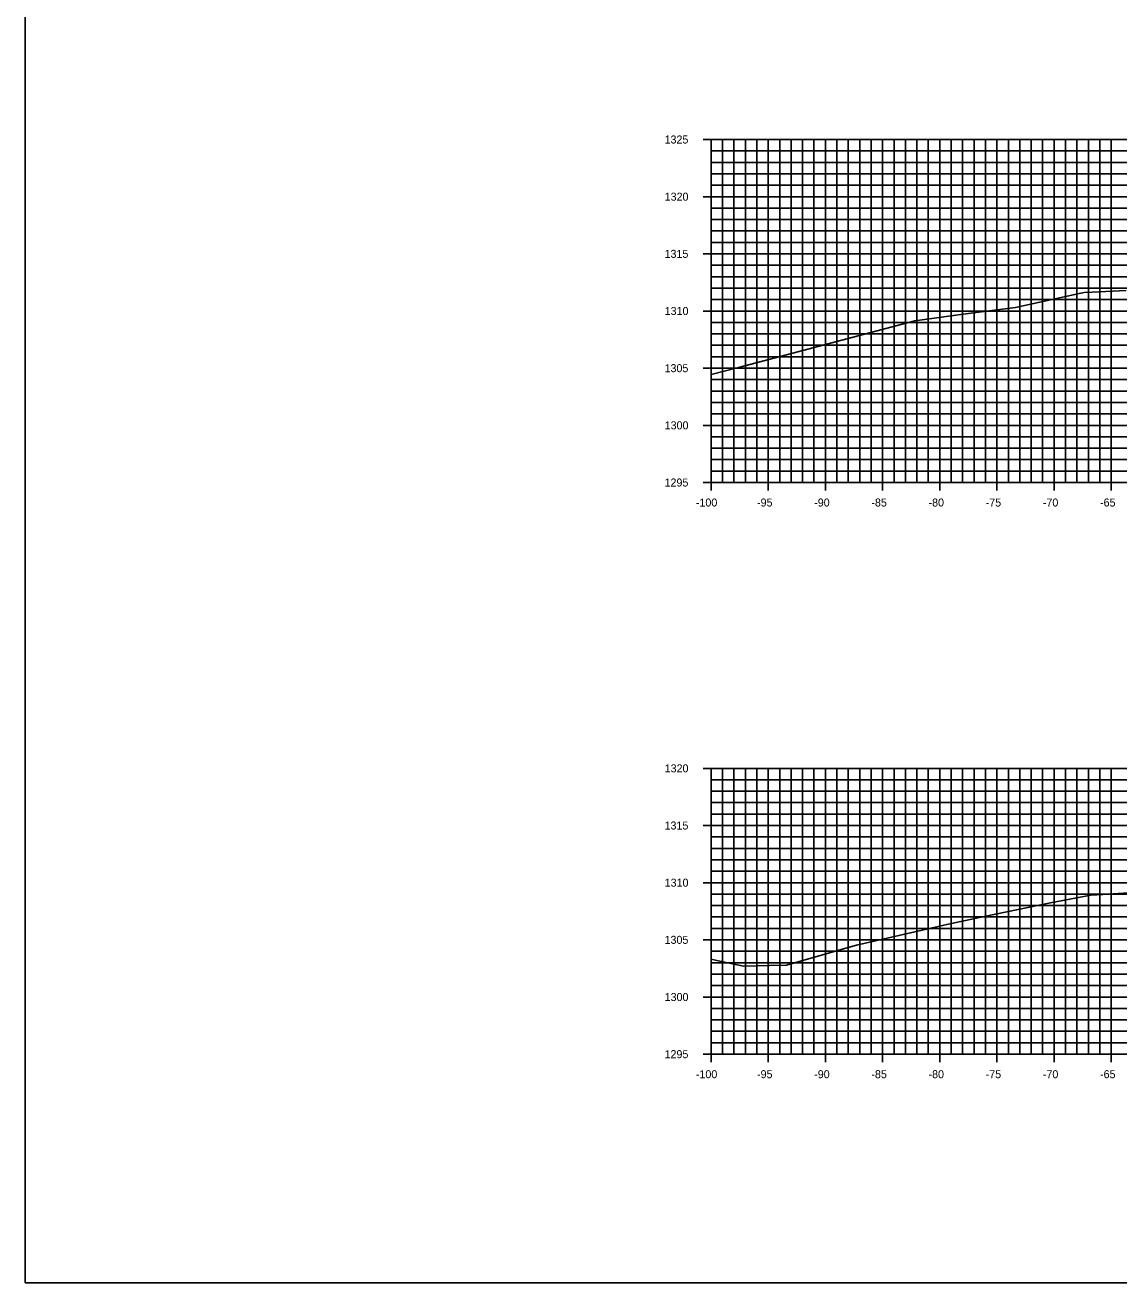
# Model space of a CAD drawing. Extents: x 674939 to 678919, y 750652 to 765176.
# Drawn here: x 678578.5 to 678674.2, y 751152.6 to 751262.6 of the extents above; entities that cross this region are included whole.
import ezdxf

# ---------------------------------------------------------------- set-up
doc = ezdxf.new("R2010")
doc.units = 0
for name, color, linetype in [('R_Axis', 7, 'Continuous'), ('R_Axis Annot', 7, 'Continuous'), ('R_Exist Surface', 7, 'Continuous'), ('R_Grid', 7, 'Continuous'), ('R_No Plot', 7, 'Continuous')]:
    doc.layers.add(name, color=color, linetype=linetype)

msp = doc.modelspace()

# ---------------------------------------------------------------- linework, layer by layer
at = {"layer": 'R_Axis'}
for p, q in [((678637.83, 751252.55), (678639.23, 751252.55)), ((678638.53, 751222.55), (678638.53, 751252.55)), ((678638.53, 751251.55), (678638.88, 751251.55)), ((678638.53, 751250.55), (678638.88, 751250.55)), ((678638.53, 751249.55), (678638.88, 751249.55)), ((678638.53, 751248.55), (678638.88, 751248.55)), ((678637.83, 751247.55), (678639.23, 751247.55)), ((678638.53, 751246.55), (678638.88, 751246.55)), ((678638.53, 751245.55), (678638.88, 751245.55)), ((678638.53, 751244.55), (678638.88, 751244.55)), ((678638.53, 751243.55), (678638.88, 751243.55)), ((678637.83, 751242.55), (678639.23, 751242.55)), ((678638.53, 751241.55), (678638.88, 751241.55)), ((678638.53, 751240.55), (678638.88, 751240.55)), ((678638.53, 751239.55), (678638.88, 751239.55)), ((678638.53, 751238.55), (678638.88, 751238.55)), ((678637.83, 751237.55), (678639.23, 751237.55)), ((678638.53, 751236.55), (678638.88, 751236.55)), ((678638.53, 751235.55), (678638.88, 751235.55)), ((678638.53, 751234.55), (678638.88, 751234.55)), ((678638.53, 751233.55), (678638.88, 751233.55)), ((678637.83, 751232.55), (678639.23, 751232.55)), ((678638.53, 751231.55), (678638.88, 751231.55)), ((678638.53, 751230.55), (678638.88, 751230.55)), ((678638.53, 751229.55), (678638.88, 751229.55)), ((678638.53, 751228.55), (678638.88, 751228.55)), ((678637.83, 751227.55), (678639.23, 751227.55)), ((678638.53, 751226.55), (678638.88, 751226.55)), ((678638.53, 751225.55), (678638.88, 751225.55)), ((678638.53, 751224.55), (678638.88, 751224.55)), ((678638.53, 751223.55), (678638.88, 751223.55)), ((678638.53, 751221.85), (678638.53, 751223.25)), ((678643.53, 751221.85), (678643.53, 751223.25)), ((678648.53, 751221.85), (678648.53, 751223.25)), ((678653.53, 751221.85), (678653.53, 751223.25)), ((678658.53, 751221.85), (678658.53, 751223.25)), ((678663.53, 751221.85), (678663.53, 751223.25)), ((678668.53, 751221.85), (678668.53, 751223.25)), ((678673.53, 751221.85), (678673.53, 751223.25)), ((678637.83, 751222.55), (678639.23, 751222.55)), ((678638.53, 751222.55), (678838.53, 751222.55)), ((678637.83, 751197.55), (678639.23, 751197.55)), ((678638.53, 751172.55), (678638.53, 751197.55)), ((678638.53, 751196.55), (678638.88, 751196.55)), ((678638.53, 751195.55), (678638.88, 751195.55)), ((678638.53, 751194.55), (678638.88, 751194.55)), ((678638.53, 751193.55), (678638.88, 751193.55)), ((678637.83, 751192.55), (678639.23, 751192.55)), ((678638.53, 751191.55), (678638.88, 751191.55)), ((678638.53, 751190.55), (678638.88, 751190.55)), ((678638.53, 751189.55), (678638.88, 751189.55)), ((678638.53, 751188.55), (678638.88, 751188.55)), ((678637.83, 751187.55), (678639.23, 751187.55)), ((678638.53, 751186.55), (678638.88, 751186.55)), ((678638.53, 751185.55), (678638.88, 751185.55)), ((678638.53, 751184.55), (678638.88, 751184.55)), ((678638.53, 751183.55), (678638.88, 751183.55)), ((678637.83, 751182.55), (678639.23, 751182.55)), ((678638.53, 751181.55), (678638.88, 751181.55)), ((678638.53, 751180.55), (678638.88, 751180.55)), ((678638.53, 751179.55), (678638.88, 751179.55)), ((678638.53, 751178.55), (678638.88, 751178.55)), ((678637.83, 751177.55), (678639.23, 751177.55)), ((678638.53, 751176.55), (678638.88, 751176.55)), ((678638.53, 751175.55), (678638.88, 751175.55)), ((678638.53, 751174.55), (678638.88, 751174.55)), ((678638.53, 751173.55), (678638.88, 751173.55)), ((678637.83, 751172.55), (678639.23, 751172.55)), ((678638.53, 751171.85), (678638.53, 751173.25)), ((678638.53, 751172.55), (678838.53, 751172.55)), ((678643.53, 751171.85), (678643.53, 751173.25)), ((678648.53, 751171.85), (678648.53, 751173.25)), ((678653.53, 751171.85), (678653.53, 751173.25)), ((678658.53, 751171.85), (678658.53, 751173.25)), ((678663.53, 751171.85), (678663.53, 751173.25)), ((678668.53, 751171.85), (678668.53, 751173.25)), ((678673.53, 751171.85), (678673.53, 751173.25))]:
    msp.add_line(p, q, dxfattribs=at)
at = {"layer": 'R_Exist Surface'}
for points in [[(678638.53, 751232.01), (678640.94, 751232.6), (678644.56, 751233.56), (678656.36, 751236.69), (678660.59, 751237.27), (678665.16, 751237.87), (678670.87, 751239.11), (678671.06, 751239.15), (678671.15, 751239.16), (678671.87, 751239.19), (678674.84, 751239.35)], [(678638.53, 751180.85), (678639.03, 751180.75), (678641.37, 751180.24), (678643.64, 751180.31), (678645.14, 751180.33), (678648.68, 751181.35), (678651.24, 751182.08), (678657, 751183.39), (678659.14, 751183.9), (678662.42, 751184.58), (678668.22, 751185.78), (678671.75, 751186.47), (678672.8, 751186.53), (678675.04, 751186.67)]]:
    msp.add_lwpolyline(points, dxfattribs=at)
at = {"layer": 'R_Grid'}
for p, q in [((678638.53, 751252.55), (678838.53, 751252.55)), ((678638.53, 751222.55), (678638.53, 751252.55)), ((678639.53, 751222.55), (678639.53, 751252.55)), ((678640.53, 751222.55), (678640.53, 751252.55)), ((678641.53, 751222.55), (678641.53, 751252.55)), ((678642.53, 751222.55), (678642.53, 751252.55)), ((678643.53, 751222.55), (678643.53, 751252.55)), ((678644.53, 751222.55), (678644.53, 751252.55)), ((678645.53, 751222.55), (678645.53, 751252.55)), ((678646.53, 751222.55), (678646.53, 751252.55)), ((678647.53, 751222.55), (678647.53, 751252.55)), ((678648.53, 751222.55), (678648.53, 751252.55)), ((678649.53, 751222.55), (678649.53, 751252.55)), ((678650.53, 751222.55), (678650.53, 751252.55)), ((678651.53, 751222.55), (678651.53, 751252.55)), ((678652.53, 751222.55), (678652.53, 751252.55)), ((678653.53, 751222.55), (678653.53, 751252.55)), ((678654.53, 751222.55), (678654.53, 751252.55)), ((678655.53, 751222.55), (678655.53, 751252.55)), ((678656.53, 751222.55), (678656.53, 751252.55)), ((678657.53, 751222.55), (678657.53, 751252.55)), ((678658.53, 751222.55), (678658.53, 751252.55)), ((678659.53, 751222.55), (678659.53, 751252.55)), ((678660.53, 751222.55), (678660.53, 751252.55)), ((678661.53, 751222.55), (678661.53, 751252.55)), ((678662.53, 751222.55), (678662.53, 751252.55)), ((678663.53, 751222.55), (678663.53, 751252.55)), ((678664.53, 751222.55), (678664.53, 751252.55)), ((678665.53, 751222.55), (678665.53, 751252.55)), ((678666.53, 751222.55), (678666.53, 751252.55)), ((678667.53, 751222.55), (678667.53, 751252.55)), ((678668.53, 751222.55), (678668.53, 751252.55)), ((678669.53, 751222.55), (678669.53, 751252.55)), ((678670.53, 751222.55), (678670.53, 751252.55)), ((678671.53, 751222.55), (678671.53, 751252.55)), ((678672.53, 751222.55), (678672.53, 751252.55)), ((678673.53, 751222.55), (678673.53, 751252.55)), ((678638.53, 751251.55), (678838.53, 751251.55)), ((678638.53, 751250.55), (678838.53, 751250.55)), ((678638.53, 751249.55), (678838.53, 751249.55)), ((678638.53, 751248.55), (678838.53, 751248.55)), ((678638.53, 751247.55), (678838.53, 751247.55)), ((678638.53, 751246.55), (678838.53, 751246.55)), ((678638.53, 751245.55), (678838.53, 751245.55)), ((678638.53, 751244.55), (678838.53, 751244.55)), ((678638.53, 751243.55), (678838.53, 751243.55)), ((678638.53, 751242.55), (678838.53, 751242.55)), ((678638.53, 751241.55), (678838.53, 751241.55)), ((678638.53, 751240.55), (678838.53, 751240.55)), ((678638.53, 751239.55), (678838.53, 751239.55)), ((678638.53, 751238.55), (678838.53, 751238.55)), ((678638.53, 751237.55), (678838.53, 751237.55)), ((678638.53, 751236.55), (678838.53, 751236.55)), ((678638.53, 751235.55), (678838.53, 751235.55)), ((678638.53, 751234.55), (678838.53, 751234.55)), ((678638.53, 751233.55), (678838.53, 751233.55)), ((678638.53, 751232.55), (678838.53, 751232.55)), ((678638.53, 751231.55), (678838.53, 751231.55)), ((678638.53, 751230.55), (678838.53, 751230.55)), ((678638.53, 751229.55), (678838.53, 751229.55)), ((678638.53, 751228.55), (678838.53, 751228.55)), ((678638.53, 751227.55), (678838.53, 751227.55)), ((678638.53, 751226.55), (678838.53, 751226.55)), ((678638.53, 751225.55), (678838.53, 751225.55)), ((678638.53, 751224.55), (678838.53, 751224.55)), ((678638.53, 751223.55), (678838.53, 751223.55)), ((678638.53, 751222.55), (678838.53, 751222.55)), ((678638.53, 751197.55), (678838.53, 751197.55)), ((678638.53, 751172.55), (678638.53, 751197.55)), ((678639.53, 751172.55), (678639.53, 751197.55)), ((678640.53, 751172.55), (678640.53, 751197.55)), ((678641.53, 751172.55), (678641.53, 751197.55)), ((678642.53, 751172.55), (678642.53, 751197.55)), ((678643.53, 751172.55), (678643.53, 751197.55)), ((678644.53, 751172.55), (678644.53, 751197.55)), ((678645.53, 751172.55), (678645.53, 751197.55)), ((678646.53, 751172.55), (678646.53, 751197.55)), ((678647.53, 751172.55), (678647.53, 751197.55)), ((678648.53, 751172.55), (678648.53, 751197.55)), ((678649.53, 751172.55), (678649.53, 751197.55)), ((678650.53, 751172.55), (678650.53, 751197.55)), ((678651.53, 751172.55), (678651.53, 751197.55)), ((678652.53, 751172.55), (678652.53, 751197.55)), ((678653.53, 751172.55), (678653.53, 751197.55)), ((678654.53, 751172.55), (678654.53, 751197.55)), ((678655.53, 751172.55), (678655.53, 751197.55)), ((678656.53, 751172.55), (678656.53, 751197.55)), ((678657.53, 751172.55), (678657.53, 751197.55)), ((678658.53, 751172.55), (678658.53, 751197.55)), ((678659.53, 751172.55), (678659.53, 751197.55)), ((678660.53, 751172.55), (678660.53, 751197.55)), ((678661.53, 751172.55), (678661.53, 751197.55)), ((678662.53, 751172.55), (678662.53, 751197.55)), ((678663.53, 751172.55), (678663.53, 751197.55)), ((678664.53, 751172.55), (678664.53, 751197.55)), ((678665.53, 751172.55), (678665.53, 751197.55)), ((678666.53, 751172.55), (678666.53, 751197.55)), ((678667.53, 751172.55), (678667.53, 751197.55)), ((678668.53, 751172.55), (678668.53, 751197.55)), ((678669.53, 751172.55), (678669.53, 751197.55)), ((678670.53, 751172.55), (678670.53, 751197.55)), ((678671.53, 751172.55), (678671.53, 751197.55)), ((678672.53, 751172.55), (678672.53, 751197.55)), ((678673.53, 751172.55), (678673.53, 751197.55)), ((678638.53, 751196.55), (678838.53, 751196.55)), ((678638.53, 751195.55), (678838.53, 751195.55)), ((678638.53, 751194.55), (678838.53, 751194.55)), ((678638.53, 751193.55), (678838.53, 751193.55)), ((678638.53, 751192.55), (678838.53, 751192.55)), ((678638.53, 751191.55), (678838.53, 751191.55)), ((678638.53, 751190.55), (678838.53, 751190.55)), ((678638.53, 751189.55), (678838.53, 751189.55)), ((678638.53, 751188.55), (678838.53, 751188.55)), ((678638.53, 751187.55), (678838.53, 751187.55)), ((678638.53, 751186.55), (678838.53, 751186.55)), ((678638.53, 751185.55), (678838.53, 751185.55)), ((678638.53, 751184.55), (678838.53, 751184.55)), ((678638.53, 751183.55), (678838.53, 751183.55)), ((678638.53, 751182.55), (678838.53, 751182.55)), ((678638.53, 751181.55), (678838.53, 751181.55)), ((678638.53, 751180.55), (678838.53, 751180.55)), ((678638.53, 751179.55), (678838.53, 751179.55)), ((678638.53, 751178.55), (678838.53, 751178.55)), ((678638.53, 751177.55), (678838.53, 751177.55)), ((678638.53, 751176.55), (678838.53, 751176.55)), ((678638.53, 751175.55), (678838.53, 751175.55)), ((678638.53, 751174.55), (678838.53, 751174.55)), ((678638.53, 751173.55), (678838.53, 751173.55)), ((678638.53, 751172.55), (678838.53, 751172.55))]:
    msp.add_line(p, q, dxfattribs=at)
at = {"layer": 'R_No Plot'}
msp.add_lwpolyline([(678578.53, 751152.55), (678918.53, 751152.55), (678918.53, 751372.55), (678578.53, 751372.55)], close=True, dxfattribs=at)

# ---------------------------------------------------------------- texts
at = {"layer": 'R_Axis Annot'}
for s, p in [('1325', (678634.46, 751252.2)), ('1320', (678634.47, 751247.2)), ('1315', (678634.46, 751242.2)), ('1310', (678634.47, 751237.2)), ('1305', (678634.46, 751232.2)), ('1300', (678634.47, 751227.2)), ('1295', (678634.46, 751222.2)), ('-100', (678637.2, 751220.45)), ('-95', (678642.55, 751220.45)), ('-90', (678647.55, 751220.45)), ('-85', (678652.55, 751220.45)), ('-80', (678657.55, 751220.45)), ('-75', (678662.55, 751220.45)), ('-70', (678667.55, 751220.45)), ('-65', (678672.55, 751220.45)), ('1320', (678634.47, 751197.2)), ('1315', (678634.46, 751192.2)), ('1310', (678634.47, 751187.2)), ('1305', (678634.46, 751182.2)), ('1300', (678634.47, 751177.2)), ('1295', (678634.46, 751172.2)), ('-100', (678637.2, 751170.45)), ('-95', (678642.55, 751170.45)), ('-90', (678647.55, 751170.45)), ('-85', (678652.55, 751170.45)), ('-80', (678657.55, 751170.45)), ('-75', (678662.55, 751170.45)), ('-70', (678667.55, 751170.45)), ('-65', (678672.55, 751170.45))]:
    msp.add_text(s, height=0.7, dxfattribs=at).set_placement(p)

doc.saveas('drawing.dxf')
